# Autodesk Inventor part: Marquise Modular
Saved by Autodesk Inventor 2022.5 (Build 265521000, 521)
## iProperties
Created: 2025-01
Part Number: Marquise Modular
Material: Generic
Document SubType Name: Modeling
Designer: AdminForWorker
Density: 1 g/cm^3
Appearance: Default
Title: Marquise Modular
Author: AdminForWorker
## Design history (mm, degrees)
feature "Marquise Modular"
body "Solid1"
